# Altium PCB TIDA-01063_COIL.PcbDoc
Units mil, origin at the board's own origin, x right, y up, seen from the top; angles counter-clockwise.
Board outline 2542.15 x 3079.41 mil, 2 copper layers (Top Layer, Bottom Layer), stack 62 mil thick; 9 components, 2 nets, 8 pads, 343 vias.
Unrouted connection lines stored in the file: 1.
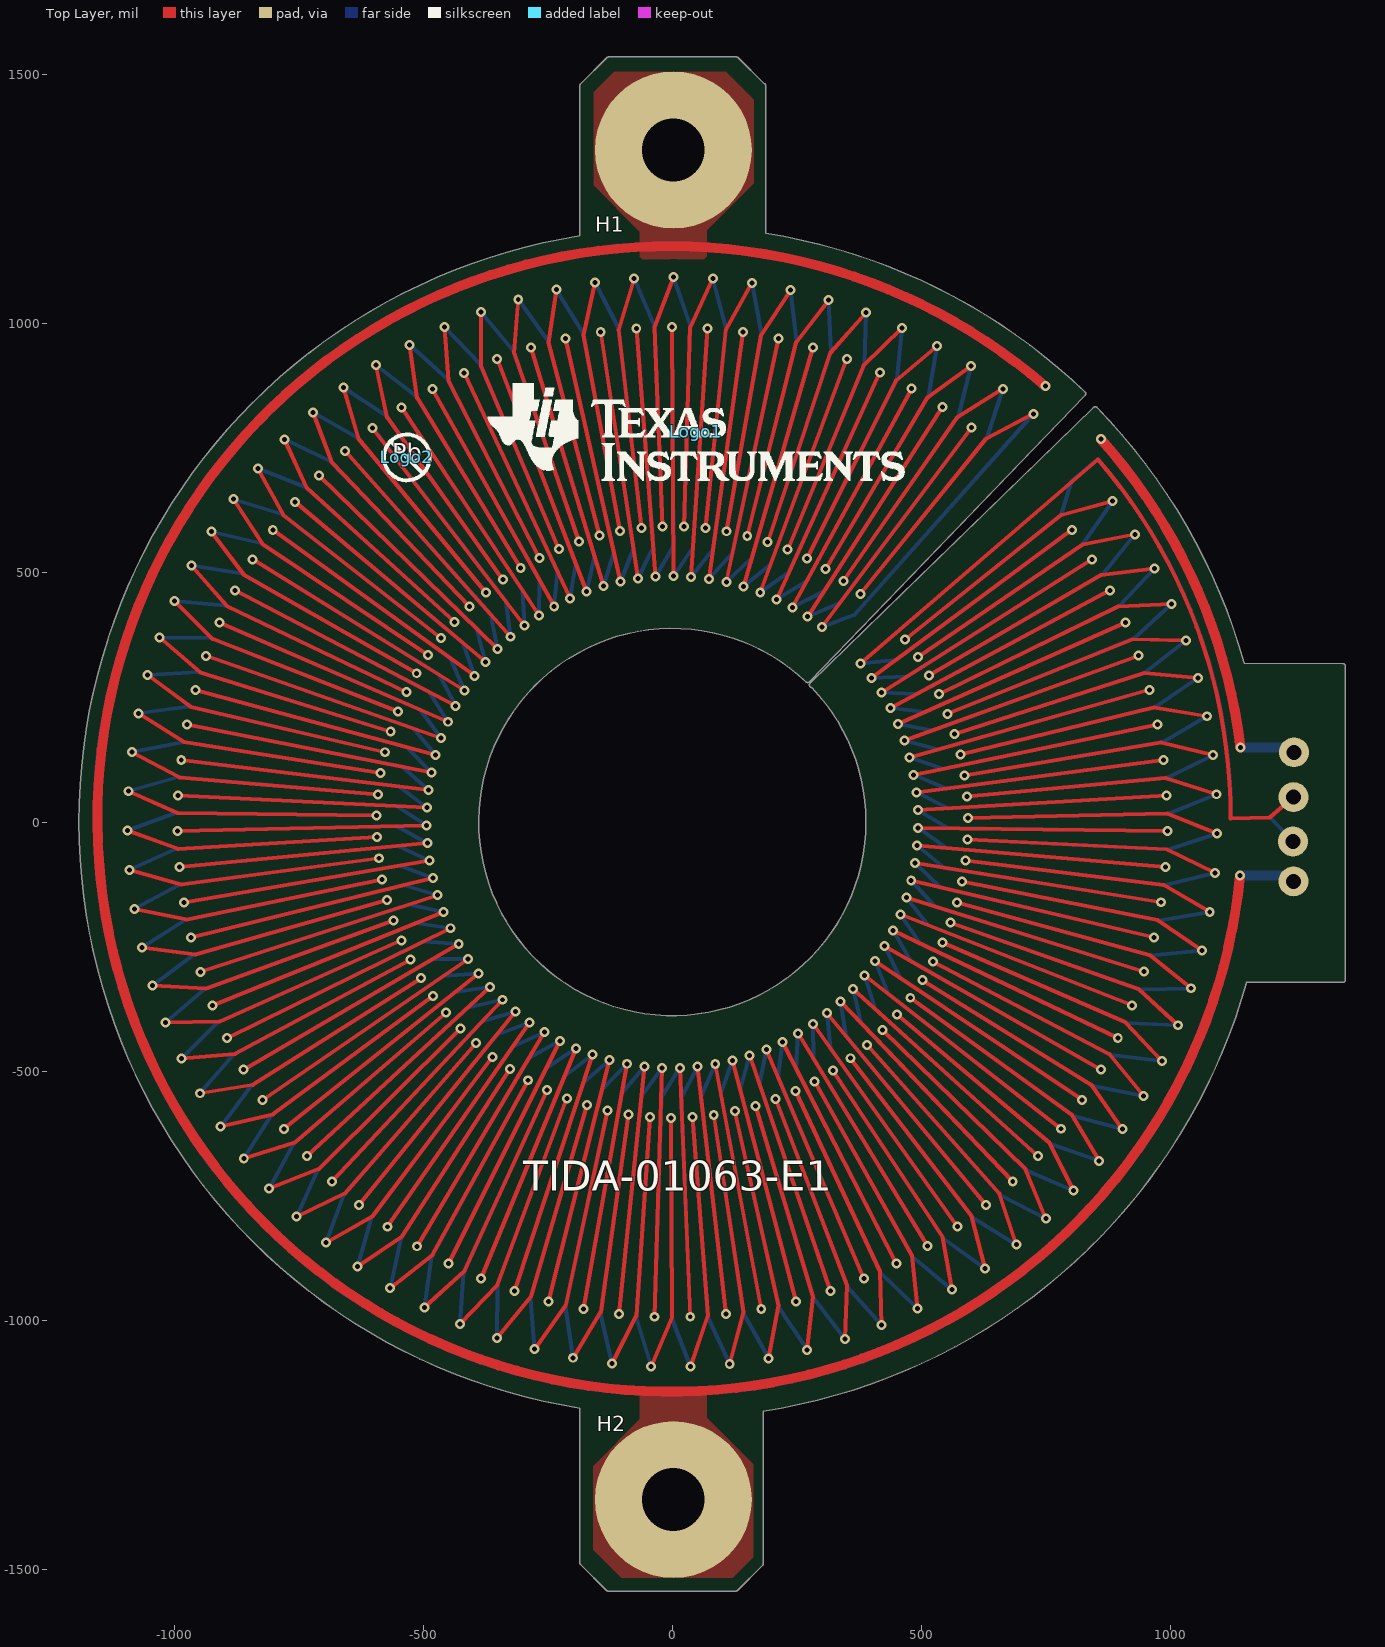
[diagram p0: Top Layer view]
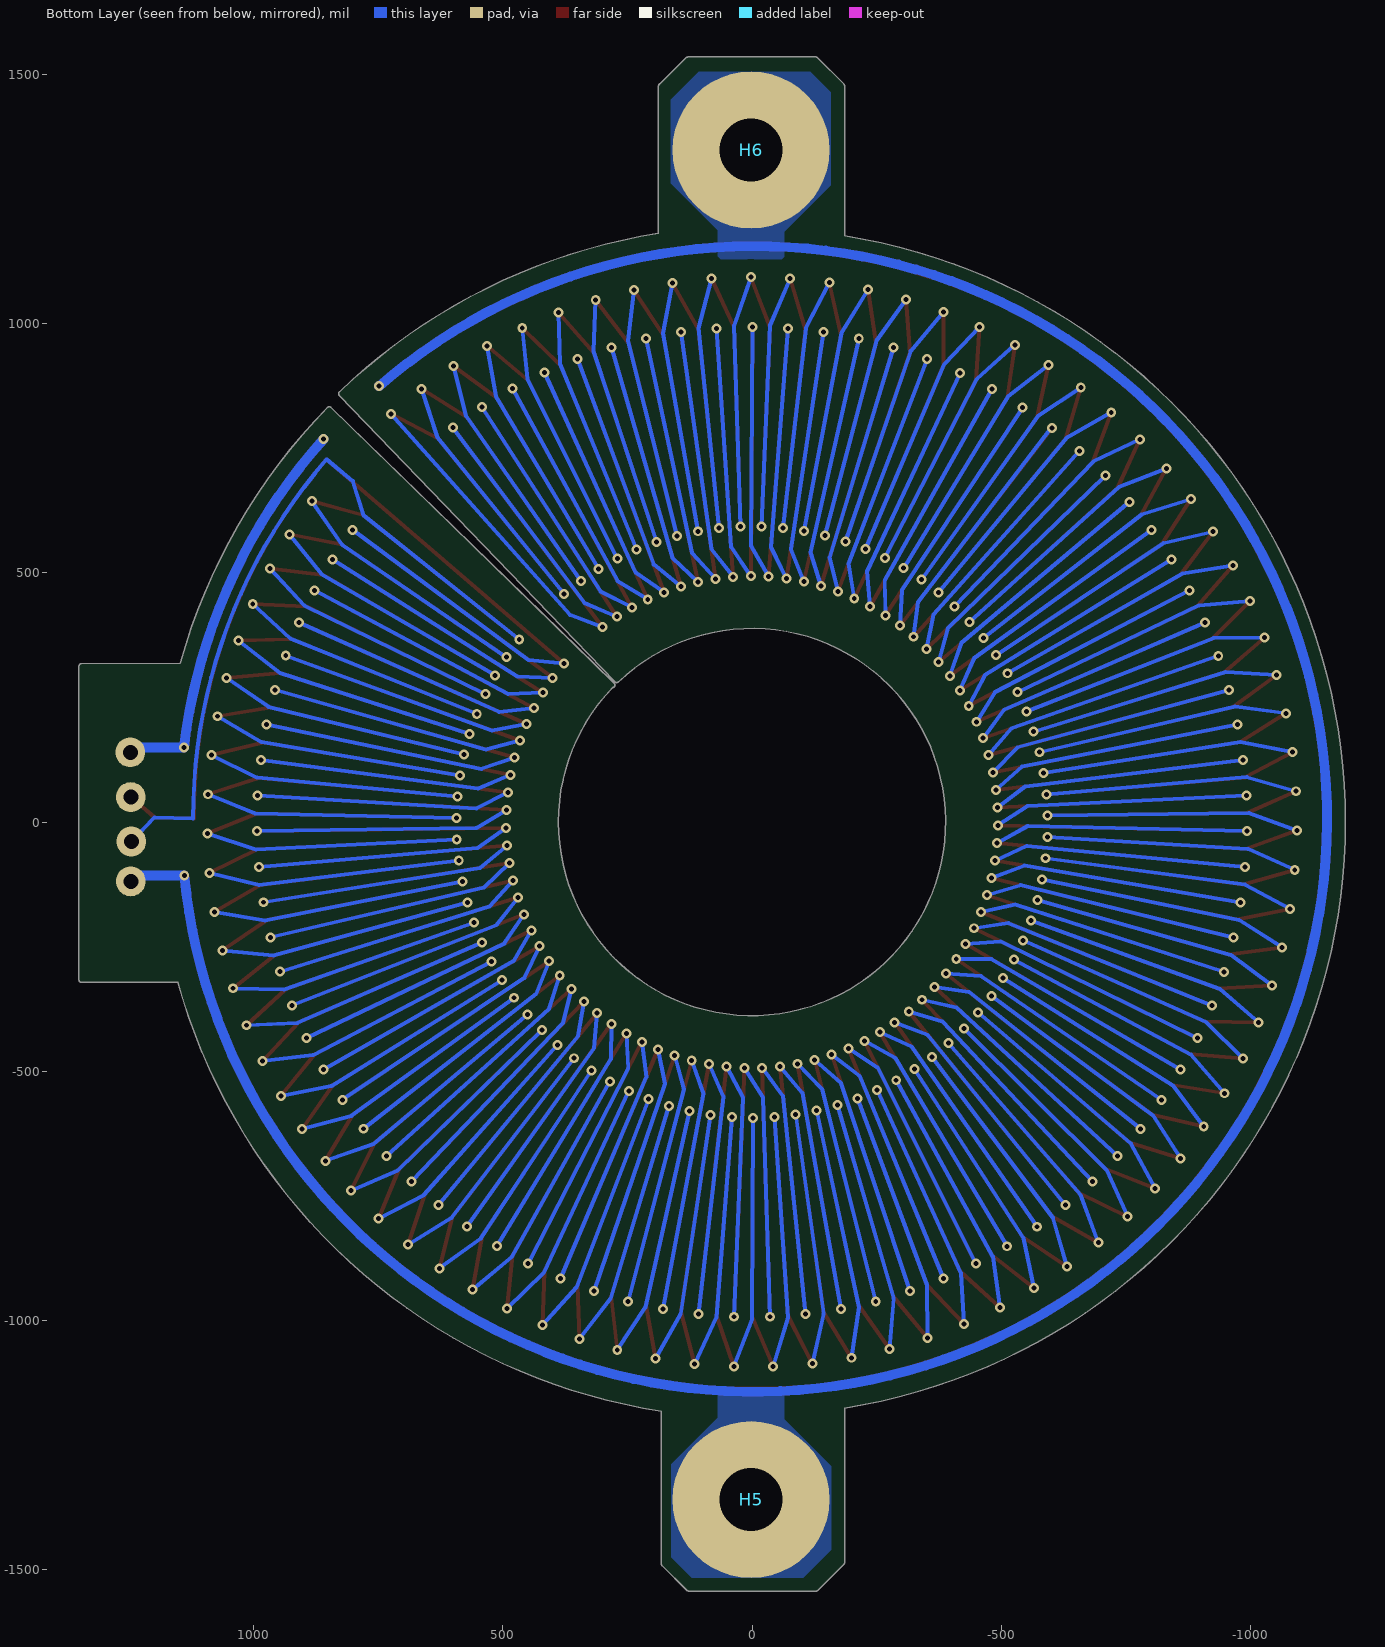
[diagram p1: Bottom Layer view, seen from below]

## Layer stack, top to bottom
Top Solder: solder mask 0.4, Solder Resist, Dk 3.5
Top Layer: signal copper 1.4
Dielectric1: core 59.2, FR-4, Dk 4.8
Bottom Layer: signal copper 1.4
Bottom Solder: solder mask 0.4, Solder Resist, Dk 3.5

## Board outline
-184.35,-1490.35 -132.55,-1542.16 -132.56,-1542.14 ccw(c-129,-1538.61) -129,-1543.63 127.61,-1543.63 ccw(c127.61,-1538.61) 131.17,-1542.14 131.16,-1542.16 180.77,-1492.55 180.75,-1492.56 ccw(c177.22,-1489) 182.24,-1489 182.24,-1182.66 ccw(c0,0) 1152.67,-321.3 1345.98,-321.94 ccw(c1346,-316.92) 1351.02,-316.92 1351.02,313 ccw(c1346,313) 1346.02,318.02 1147.66,318.86 ccw(c0,0) 852.24,832.16 ccw(c848.65,828.65) 845.14,832.23 845.15,832.25 845.14,832.23 277.56,279.62 ccw(c280.89,275.87) 277.22,279.3 276.5,278.59 ccw(c280,275) 279.6,270 cw(c0,0) 388.69,0 cw(c0,0) 268.15,281.37 ccw(c271.61,285) 275.23,281.53 828.44,856.43 ccw(c824.82,859.91) 829.84,859.91 ccw(c824.82,859.91) 828.3,863.53 ccw(c0,0) 187.71,1181.75 187.71,1477.69 ccw(c182.69,1477.69) 184.13,1482.5 132.31,1534.31 132.33,1534.3 ccw(c128.77,1530.77) 128.77,1535.78 -128,1535.78 ccw(c-128,1530.77) -131.56,1534.3 -131.55,1534.31 -184.43,1481.43 -184.41,1481.45 ccw(c-180.88,1477.88) -185.9,1477.88 -185.9,1176.54 ccw(c0,0) -185.82,-1176.55 -185.82,-1486.81 ccw(c-180.81,-1486.81)

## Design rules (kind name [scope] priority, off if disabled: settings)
AcuteAngle [All] p1: minimum=4.50000000000000E+0001 checktracksonly=FALSE
AssemblyTestPointUsage [All] p1: valid=2
Clearance Clearance_BoardEdge_MountingHoles [OnCopper and InComponentClass('Mounting Holes') vs IsKeepOut] p1: gap=40
Clearance Clearance_BoardEdge_Poly [OnCopper and InPoly vs IsKeepOut] p2: gap=25
Clearance Clearance_BoardEdge [OnCopper and Not InComponentClass('Logo') and not InComponentClass('FiducialMark') and not InRegion(1000,500,4000,800) and Not IsKeepout vs IsKeepOut] p3: gap=75
Clearance Clearance_Poly [InPolygon] p4: gap=25
Clearance [All] p5: gap=5
ComponentClearance [All] p1: gap=5 collisioncheckmode=3 verticalgap=5 showdistances=FALSE
DiffPairsRouting [All] p1: maxlimit=100 minlimit=10 mostfreqgap=10 toplayer_minwidth=15 toplayer_maxwidth=15 toplayer_prefwidth=15 bottomlayer_minwidth=15 bottomlayer_maxwidth=15 bottomlayer_prefwidth=15 maxuncoupledlength=1000
FabricationTestPointUsage TestPointUsage [All] p1: valid=2 allowmultiple=FALSE
FabricationTestpoint Testpoint [All] p1: side=3 testpointundercomponent=TRUE minsize=40 maxsize=100 preferedsize=60 minholesize=0 maxholesize=40 preferedholesize=32 testpointgrid=1 allowsidetop=TRUE allowsidebottom=TRUE usegrid=TRUE gridtolerance=0.01
FanoutControl Fanout_LCC [IsLCC] p1: bgadir=Out bgaviamode=Centered fanoutstyle=Auto fanoutdirection=Alternating viagrid=1 // Fanout_LCC (Default Rule)
FanoutControl Fanout_BGA [IsBGA] p2: bgadir=Out bgaviamode=Centered fanoutstyle=Auto fanoutdirection=Alternating viagrid=1 // Fanout_BGA (Default Rule)
FanoutControl Fanout_Default [All] p4: bgadir=Out bgaviamode=Centered fanoutstyle=Auto fanoutdirection=Alternating viagrid=1 // Fanout_Default (Default Rule)
FanoutControl Fanout_Small [(CompPinCount < 5)] p5: bgadir=Out bgaviamode=Centered fanoutstyle=Auto fanoutdirection=OutThenIn viagrid=1 // Fanout_Small (Default Rule)
HoleSize [All] p1: absolutevalues=TRUE maxlimit=251 minlimit=8 maxpercent=80.000 minpercent=20.000
MinimumAnnularRing MinimumAnnularRing_ThermalPadVias [IsVia and InAnyComponent] p1: minimumring=5.91
MinimumAnnularRing [All] p2: minimumring=5
MinimumSolderMaskSliver MinimumSolderMaskSliver_Logo [InComponentClass('Logo') vs InComponentClass('Logo')] p1: minsoldermaskwidth=0.7
MinimumSolderMaskSliver [All] p2: minsoldermaskwidth=3.94
PlaneConnect [All] p1: planeconnectstyle=Direct reliefexpansion=10 reliefentries=4 reliefconductorwidth=10 reliefairgap=10
PolygonConnect [All] p1: connectstyle=Direct reliefconductorwidth=10 reliefentries=4 polygonreliefangle="90 Angle" airgapwidth=10
RoutingVias ThermalPadVias [IsVia and InAnyComponent] p1: holewidth=7.87 width=19.68 viastyle="Through Hole" minholewidth=7.87 minwidth=19.68 maxholewidth=12.99 maxwidth=23.62
RoutingVias [All] p2: holewidth=16 width=32 viastyle="Through Hole" minholewidth=10 minwidth=20 maxholewidth=40 maxwidth=65
SilkToBoardRegionClearance [Not ((IsComment or IsDesignator) And (Hide <> 'False')) and not InRegion(1000,500,4000,800)] p1:
SilkToSilkClearance SilkToSilkClearance_Pb-FreeLogo [(HasFootprint('Pb-Free_Overlay_Medium') OR HasFootprint('Pb-Free_Overlay_Small')) vs (HasFootprint('Pb-Free_Overlay_Medium') OR HasFootprint('Pb-Free_Overlay_Small'))] p1: silktosilkclearance=0
SilkToSilkClearance [All] p2: silktosilkclearance=4
SilkToSolderMaskClearance SilkToComonentPadClearance [IsPad and InAnycomponent] p1: minsilkscreentomaskgap=5 clearancetoexposedcopper=TRUE
SilkToSolderMaskClearance "Silk to Solder Mask Opening" [All] p2: minsilkscreentomaskgap=4 clearancetoexposedcopper=FALSE
SolderMaskExpansion [All] p1: expansion=1.97
UnpouredPolygon [All] p1: allowunpoured=FALSE
Width [All] p1: maxlimit=100 minlimit=6 preferedwidth=10 checkconnectedcopper=TRUE
14 further rules are at their usual default settings.

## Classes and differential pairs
component class AssemblyNote: ZZ2 ZZ3 ZZ4
component class Logo: Logo1
component class "Mounting Holes": H1 H2

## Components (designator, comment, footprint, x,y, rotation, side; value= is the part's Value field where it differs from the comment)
H1 "NY PMS 440 0025 PH" "NY PMS 440 0025 PH" 2,1349 r90 top
H2 "NY PMS 440 0025 PH" "NY PMS 440 0025 PH" 2,-1360 r90 top
H5 "1902C" Keystone_1902C 2,-1360 r90 bottom
H6 "1902C" Keystone_1902C 2,1349 r90 bottom
Logo1 "Texas Instruments" TI_Stacked_Overlay_Small 48,783 r0 top
Logo2 "Pb-Free Symbol" Pb-Free_Overlay_Small -533,732 r0 top
ZZ2 "These assemblies are ESD sensitive, ESD precautions shall be observed." AssemblyNote -671,-1969 r0 top
ZZ3 "These assemblies must be clean and free from flux and all contaminants. Use of no clean flux is not acceptable." AssemblyNote -670,-2068 r0 top
ZZ4 "These assemblies must comply with workmanship standards IPC-A-610 Class 2, unless otherwise specified." AssemblyNote -670,-2148 r0 top

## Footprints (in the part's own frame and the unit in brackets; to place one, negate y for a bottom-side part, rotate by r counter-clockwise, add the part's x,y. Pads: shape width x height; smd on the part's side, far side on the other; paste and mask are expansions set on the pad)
AssemblyNote [mil] "Assembly Note"
Keystone_1902C [mil] "Hex Standoff, 4-40 threaded, nylon"
  round 1 on Mech4: 0(0,0)
  body extent -145,-126 146,126, height 501
"NY PMS 440 0025 PH" [mm] "4-40 nylon screw and mounting hole"
  round 8 hole 3.2: 1(0,0)
  body extent -3.3,-3.3 3.3,3.3, height 2.69
Pb-Free_Overlay_Small [mil]
  silkscreen extent -46,-46 46,46
TI_Stacked_Overlay_Small [mil]
  silkscreen extent -418,-98 418,98

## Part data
H1 H2: "Machine Screw, Round, #4-40 x 1/4, Nylon, Philips panhead"
H5 H6: "Standoff, Hex, 0.5\"L #4-40 Nylon"
Logo1: library part TI_Logo, "Texas Instrument Corporate Signature"
Logo2: library part Pb-Free
ZZ2 ZZ3 ZZ4: library part AssemblyNote

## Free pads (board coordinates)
  round 60 hole 30: 0(1247,-119) 0(1247,50) 0(1248,140) 1(1246,-39)

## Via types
v1: diameter 20, hole 10, Top Layer to Bottom Layer, 343 vias

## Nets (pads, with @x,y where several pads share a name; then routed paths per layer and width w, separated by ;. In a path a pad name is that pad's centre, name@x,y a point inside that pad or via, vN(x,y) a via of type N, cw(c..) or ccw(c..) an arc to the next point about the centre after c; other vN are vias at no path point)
COIL: pad.0@1247,50 pad.1 | length 174207.6
  Top Layer w8: v1(-1093.57,-17.08) -992.25,-53.65 v1(-592.94,-29.99) ; v1(-1091.95,61.85) -993.54,18.07 v1(-593.56,12.87) ; v1(-1089.49,-95.93) -985.8,-125.09 v1(-589.23,-72.68) ; v1(-1084.64,140.47) -989.64,89.7 v1(-591.09,55.66) ; v1(-1079.73,-174.28) -974.2,-195.89 v1(-582.46,-115) ; v1(-1071.68,218.35) -980.59,160.86 v1(-585.53,98.15) ; v1(-1064.34,-251.72) -957.53,-265.66 v1(-572.64,-156.72) ; v1(-1053.14,295.09) -966.43,231.18 v1(-576.92,140.14) ; v1(-1043.41,-327.84) -935.87,-334.04 v1(-559.84,-197.62) ; v1(-1029.11,370.3) -947.24,300.3 v1(-565.31,181.39) ; v1(-1017.04,-402.26) -909.34,-400.69 v1(-544.13,-237.5) ; v1(-999.71,443.57) -923.11,367.85 v1(-550.75,221.7) ; v1(-993.53,-18.35) v1(-493.66,-6.53) ; v1(-992.27,53.37) v1(-492.84,29.1) ; v1(-989.62,-89.98) v1(-491.9,-42.13) ; v1(-985.83,124.82) v1(-489.46,64.58) ; v1(-985.37,-474.59) -878.06,-465.24 v1(-525.58,-276.13) ; v1(-980.55,-161.13) v1(-487.58,-77.5) ; v1(-974.26,195.61) v1(-483.53,99.72) ; v1(-966.37,-231.45) v1(-480.72,-112.48) ; v1(-965.11,514.54) -894.16,433.49 v1(-533.32,260.86) ; v1(-957.61,265.39) v1(-475.07,134.34) ; v1(-948.56,-544.43) -842.21,-527.38 v1(-504.29,-313.33) ; v1(-947.15,-300.56) v1(-471.35,-146.86) ; v1(-935.97,333.78) v1(-464.14,168.26) ; v1(-925.47,582.82) -860.56,496.87 v1(-513.12,298.65) ; v1(-923,-368.11) v1(-459.53,-180.48) ; v1(-909.45,400.43) v1(-450.79,201.31) ; v1(-906.82,-611.45) -801.97,-586.76 v1(-480.37,-348.89) ; v1(-894.04,-433.74) v1(-445.31,-213.17) ; v1(-881.01,648.07) -822.47,557.65 v1(-490.23,334.89) ; v1(-878.19,465) v1(-435.1,233.31) ; v1(-860.42,-497.11) v1(-428.77,-244.74) ; v1(-860.34,-675.27) -757.55,-643.09 v1(-453.95,-382.64) ; v1(-842.36,527.14) v1(-417.13,264.09) ; v1(-831.97,709.94) -780.1,615.53 v1(-464.8,369.38) ; v1(-822.32,-557.88) v1(-410,-275.03) ; v1(-809.38,-735.58) -709.18,-696.06 v1(-425.16,-414.39) ; v1(-802.13,586.54) v1(-396.99,293.49) ; v1(-779.93,-615.75) v1(-389.09,-303.89) ; v1(-778.58,768.11) -733.66,670.21 v1(-436.94,401.95) ; v1(-757.73,642.87) v1(-374.79,321.37) ; v1(-754.21,-792.05) -657.12,-745.41 v1(-394.16,-443.98) ; v1(-733.48,-670.41) v1(-366.15,-331.17) ; v1(-721.14,822.28) -683.4,721.39 v1(-406.8,432.43) ; v1(-709.38,695.86) v1(-350.63,347.57) ; v1(-695.1,-844.4) -601.63,-790.87 v1(-361.1,-471.26) ; v1(-683.2,-721.58) v1(-341.31,-356.72) ; v1(-659.94,872.16) -629.58,768.81 v1(-374.55,460.65) ; v1(-657.33,745.23) v1(-324.64,371.96) ; v1(-632.38,-892.35) -543.01,-832.21 v1(-326.16,-496.08) ; v1(-629.36,-768.99) v1(-314.68,-380.41) ; v1(-601.85,790.7) v1(-296.96,394.41) ; v1(-595.3,917.49) -572.48,812.23 v1(-340.34,486.47) ; v1(-572.25,-812.39) v1(-286.42,-402.12) ; v1(-566.35,-935.64) -481.56,-869.22 v1(-289.52,-518.32) ; v1(-543.24,832.06) v1(-267.73,414.8) ; v1(-527.56,958.05) -512.39,851.41 v1(-304.36,509.75) ; v1(-512.15,-851.55) v1(-256.66,-421.74) ; v1(-497.38,-974.06) -417.6,-901.69 v1(-251.38,-537.86) ; v1(-481.8,869.08) v1(-237.11,433.04) ; v1(-457.07,993.61) -449.63,886.16 v1(-266.79,530.38) ; v1(-449.38,-886.28) v1(-225.57,-439.16) ; v1(-425.81,-1007.4) -351.46,-929.47 v1(-211.92,-554.59) ; v1(-417.85,901.58) v1(-205.25,449.01) ; v1(-384.27,-916.39) v1(-193.3,-454.29) ; v1(-384.2,1024) -384.53,916.28 v1(-227.83,548.25) ; v1(-352.03,-1035.5) -283.49,-952.4 v1(-171.36,-568.43) ; v1(-351.72,929.37) v1(-172.32,462.65) ; v1(-317.16,-941.73) v1(-160.02,-467.05) ; v1(-309.33,1049.05) -317.43,941.64 v1(-187.69,563.25) ; v1(-283.76,952.33) v1(-138.5,473.88) ; v1(-276.41,-1058.2) -214.04,-970.37 v1(-129.91,-579.31) ; v1(-248.4,-962.15) v1(-125.91,-477.37) ; v1(-232.84,1068.63) -248.67,962.08 v1(-146.56,575.33) ; v1(-214.31,970.31) v1(-103.95,482.63) ; v1(-199.35,-1075.38) -143.48,-983.29 v1(-87.77,-587.18) ; v1(-178.34,-977.57) v1(-91.15,-485.21) ; v1(-155.14,1082.64) -178.61,977.52 v1(-104.68,584.4) ; v1(-143.76,983.25) v1(-68.86,488.87) ; v1(-121.25,-1086.96) -72.17,-991.08 v1(-45.19,-591.98) ; v1(-107.35,-987.88) v1(-55.91,-490.53) ; v1(-76.64,1091.01) -107.63,987.85 v1(-62.24,590.43) ; v1(-72.45,991.06) v1(-33.42,492.57) ; v1(-42.52,-1092.87) -0.49,-993.7 v1(-2.36,-593.7) ; v1(-35.81,-993.06) v1(-20.37,-493.28) ; v1(-19.49,593.38) -36.08,993.05 v1(2.27,1093.7) ; v1(-0.76,993.7) v1(2.21,493.7) ; v1(15.27,-493.46) v1(35.93,-993.05) ; v1(23.37,593.24) 35.65,993.06 v1(81.17,1090.68) ; v1(36.43,-1093.09) 71.2,-991.15 v1(40.47,-592.32) ; v1(37.82,492.25) v1(70.93,991.17) ; v1(50.83,-491.08) v1(107.47,-987.87) ; v1(66.11,590.01) 107.2,987.9 v1(159.64,1081.99) ; v1(73.23,488.24) v1(142.25,983.47) ; v1(83.1,-587.86) 142.52,-983.43 v1(115.2,-1087.62) ; v1(86.12,-486.13) v1(178.46,-977.54) ; v1(108.26,481.68) v1(212.82,970.64) ; v1(108.5,583.7) 178.19,977.59 v1(237.28,1067.65) ; v1(120.97,-478.65) v1(248.52,-962.12) ; v1(125.29,-580.33) 213.09,-970.58 v1(193.36,-1076.47) ; v1(142.73,472.62) v1(282.29,952.76) ; v1(150.33,574.35) 248.25,962.19 v1(313.68,1047.75) ; v1(155.18,-468.68) v1(317.28,-941.69) ; v1(166.83,-569.78) 282.56,-952.68 v1(270.51,-1059.72) ; v1(176.45,461.09) v1(350.29,929.91) ; v1(188.59,-456.26) v1(384.39,-916.34) ; v1(191.37,562.01) 317.02,941.78 v1(388.45,1022.39) ; v1(207.5,-556.26) 350.55,-929.81 v1(346.26,-1037.44) ; v1(209.26,447.16) v1(416.46,902.22) ; v1(221.01,-441.47) v1(449.49,-886.23) ; v1(231.41,546.74) 384.13,916.45 v1(461.2,991.7) ; v1(240.97,430.9) v1(480.47,869.82) ; v1(247.09,-539.84) 416.72,-902.1 v1(420.2,-1009.76) ; v1(252.29,-424.37) v1(512.25,-851.49) ; v1(270.25,528.62) 449.24,886.35 v1(531.54,955.85) ; v1(271.43,412.39) v1(541.96,832.9) ; v1(282.24,-405.07) v1(572.35,-812.32) ; v1(285.39,-520.61) 480.71,-869.69 v1(491.95,-976.81) ; v1(300.47,391.74) v1(600.64,791.63) ; v1(307.69,507.75) 512.02,851.63 v1(599.11,915.01) ; v1(310.73,-383.65) v1(629.46,-768.91) ; v1(322.2,-498.66) 542.2,-832.74 v1(561.14,-938.78) ; v1(337.6,-360.23) v1(683.29,-721.5) ; v1(343.51,484.23) 572.12,812.48 v1(663.56,869.41) ; v1(357.34,-474.12) 600.86,-791.46 v1(627.4,-895.85) ; v1(362.71,-334.94) v1(733.56,-670.32) ; v1(377.55,458.19) 629.24,769.09 v1(724.55,819.27) ; v1(377.64,318) 854,728.1 cw(c26.77,12.65) 1120.45,7.54 1199.46,9.54 pad.0@1247,50 ; v1(385.92,-307.9) v1(780,-615.66) ; v1(390.61,-447.1) 656.39,-746.05 v1(690.39,-848.26) ; v1(400.01,289.37) v1(802.06,586.63) ; v1(407.13,-279.26) v1(822.39,-557.78) ; v1(419.84,259.76) v1(842.29,527.24) ; v1(421.85,-417.76) 708.5,-696.75 v1(749.79,-796.24) ; v1(426.22,-249.16) v1(860.48,-497) ; v1(437.49,228.79) v1(878.13,465.1) ; v1(443.08,-217.76) v1(894.1,-433.63) ; v1(450.89,-386.24) 756.92,-643.83 v1(805.28,-740.07) ; v1(452.85,196.63) v1(909.4,400.54) ; v1(457.64,-185.23) v1(923.05,-368) ; v1(465.86,163.45) v1(935.92,333.89) ; v1(467.2,366.33) 779.83,615.87 v1(883.7,644.4) ; v1(469.81,-151.73) v1(947.19,-300.45) ; v1(476.44,129.42) v1(957.57,265.5) ; v1(477.58,-352.7) 801.4,-587.54 v1(856.57,-680.05) ; v1(479.53,-117.45) v1(966.4,-231.33) ; v1(484.53,94.71) v1(974.23,195.73) ; v1(486.75,-82.55) v1(980.57,-161.01) ; v1(490.1,59.51) v1(985.81,124.94) ; v1(491.44,-47.22) v1(989.63,-89.85) ; v1(492.88,330.98) 823.02,556.85 v1(928.7,577.66) ; v1(493.12,24) v1(992.26,53.5) ; v1(493.56,-11.64) v1(993.53,-18.23) ; v1(501.78,-317.33) 841.69,-528.2 v1(903.4,-616.49) ; v1(515.48,294.56) 861.05,496.02 v1(967.96,509.16) ; v1(523.36,-280.31) 877.61,-466.1 v1(945.52,-549.71) ; v1(535.38,256.6) 894.59,432.61 v1(1002.17,438) ; v1(542.22,-241.82) 908.94,-401.57 v1(982.71,-480.06) ; v1(552.5,217.31) 923.47,366.95 v1(1031.15,364.56) ; v1(558.25,-202.07) 935.55,-334.96 v1(1014.78,-407.92) ; v1(566.74,176.89) 947.53,299.37 v1(1054.77,289.22) ; v1(571.38,-161.27) 957.27,-266.59 v1(1041.57,-333.65) ; v1(578.02,135.54) 966.66,230.24 v1(1072.88,212.38) ; v1(581.52,-119.63) 974.01,-196.84 v1(1062.92,-257.64) ; v1(586.29,93.49) 980.75,159.9 v1(1085.41,134.43) ; v1(588.64,-77.37) 985.67,-126.06 v1(1078.74,-180.29) ; v1(591.51,50.95) 989.73,88.73 v1(1092.28,55.77) ; v1(592.69,-34.7) 992.2,-54.62 v1(1088.93,-102) ; v1(593.64,8.14) 993.55,17.1 v1(1093.46,-23.17)
  Bottom Layer w8: v1(-1093.57,-17.08) -997.22,18.12 v1(-593.56,12.87) ; v1(-1091.95,61.85) -993.32,90.01 v1(-591.09,55.66) ; v1(-1089.49,-95.93) -995.93,-53.87 v1(-592.94,-29.99) ; v1(-1084.64,140.47) -980.59,160.86 v1(-585.53,98.15) ; v1(-1079.73,-174.28) -989.45,-125.58 v1(-589.23,-72.68) ; v1(-1071.68,218.35) -970.03,232.02 v1(-576.92,140.14) ; v1(-1064.34,-251.72) -977.81,-196.63 v1(-582.46,-115) ; v1(-1053.14,295.09) -950.76,301.4 v1(-565.31,181.39) ; v1(-1043.41,-327.84) -961.08,-266.66 v1(-572.64,-156.72) ; v1(-1029.11,370.3) -926.54,369.2 v1(-550.75,221.7) ; v1(-1017.04,-402.26) -939.34,-335.3 v1(-559.84,-197.62) ; v1(-999.71,443.57) -897.49,435.08 v1(-533.32,260.86) ; v1(-993.53,-18.35) -553.64,-7.95 v1(-491.9,-42.13) ; v1(-992.27,53.37) -552.77,32.01 v1(-493.66,-6.53) ; v1(-989.62,-89.98) -551.63,-47.87 v1(-487.58,-77.5) ; v1(-985.83,124.82) -549.02,71.81 v1(-492.84,29.1) ; v1(-985.37,-474.59) -912.7,-402.19 v1(-544.13,-237.5) ; v1(-980.55,-161.13) -546.74,-87.54 v1(-480.72,-112.48) ; v1(-974.26,195.61) -542.41,111.23 v1(-489.46,64.58) ; v1(-966.37,-231.45) -539,-126.75 v1(-471.35,-146.86) ; v1(-965.11,514.54) -863.76,498.69 v1(-513.12,298.65) ; v1(-957.61,265.39) -532.98,150.07 v1(-483.53,99.72) ; v1(-948.56,-544.43) -881.31,-466.99 v1(-525.58,-276.13) ; v1(-947.15,-300.56) -528.45,-165.31 v1(-459.53,-180.48) ; v1(-935.97,333.78) -520.76,188.13 v1(-475.07,134.34) ; v1(-925.47,582.82) -825.54,559.71 v1(-490.23,334.89) ; v1(-923,-368.11) -515.15,-203 v1(-445.31,-213.17) ; v1(-909.45,400.43) -505.83,225.21 v1(-464.14,168.26) ; v1(-906.82,-611.45) -845.32,-529.35 v1(-504.29,-313.33) ; v1(-894.04,-433.74) -499.16,-239.63 v1(-428.77,-244.74) ; v1(-881.01,648.07) -783.01,617.8 v1(-464.8,369.38) ; v1(-878.19,465) -488.27,261.11 v1(-450.79,201.31) ; v1(-860.42,-497.11) -480.57,-275.02 v1(-410,-275.03) ; v1(-860.34,-675.27) -804.93,-588.95 v1(-480.37,-348.89) ; v1(-842.36,527.14) -468.16,295.65 v1(-435.1,233.31) ; v1(-831.97,709.94) -736.4,672.68 v1(-436.94,401.95) ; v1(-822.32,-557.88) -459.48,-308.97 v1(-389.09,-303.89) ; v1(-809.38,-735.58) -760.35,-645.49 v1(-453.95,-382.64) ; v1(-802.13,586.54) -445.61,328.66 v1(-417.13,264.09) ; v1(-779.93,-615.75) -435.99,-341.32 v1(-366.15,-331.17) ; v1(-778.58,768.11) -685.95,724.05 v1(-406.8,432.43) ; v1(-757.73,642.87) -420.74,359.95 v1(-396.99,293.49) ; v1(-754.21,-792.05) -711.8,-698.66 v1(-425.16,-414.39) ; v1(-733.48,-670.41) -410.23,-371.88 v1(-341.31,-356.72) ; v1(-721.14,822.28) -631.93,771.65 v1(-374.55,460.65) ; v1(-709.38,695.86) -393.57,389.47 v1(-374.79,321.37) ; v1(-695.1,-844.4) -659.54,-748.19 v1(-394.16,-443.98) ; v1(-683.2,-721.58) -382.34,-400.51 v1(-314.68,-380.41) ; v1(-659.94,872.16) -574.62,815.23 v1(-340.34,486.47) ; v1(-657.33,745.23) -364.56,416.75 v1(-350.63,347.57) ; v1(-632.38,-892.35) -603.85,-793.82 v1(-361.1,-471.26) ; v1(-629.36,-768.99) -352.45,-427.04 v1(-286.42,-402.12) ; v1@-600.74,791.42 -333.55,441.96 v1(-324.64,371.96) ; v1(-595.3,917.49) -514.31,854.56 v1(-304.36,509.75) ; v1(-572.25,-812.39) -320.72,-451.36 v1(-256.66,-421.74) ; v1(-566.35,-935.64) -545.01,-835.31 v1(-326.16,-496.08) ; v1(-543.24,832.06) -300.76,464.9 v1(-296.96,394.41) ; v1(-527.56,958.05) -451.32,889.44 v1(-266.79,530.38) ; v1(-512.15,-851.55) -287.32,-473.32 v1(-225.57,-439.16) ; v1(-497.38,-974.06) -483.33,-872.45 v1(-289.52,-518.32) ; v1(-481.8,869.08) -266.47,485.36 v1(-267.73,414.8) ; v1(-457.07,993.61) -385.98,919.68 v1(-227.83,548.25) ; v1(-449.38,-886.28) -252.43,-492.81 v1(-193.3,-454.29) ; v1(-425.81,-1007.4) -419.13,-905.05 v1(-251.38,-537.86) ; v1(-417.85,901.58) -230.76,503.32 v1(-237.11,433.04) ; v1(-384.27,-916.39) -216.22,-509.74 v1(-160.02,-467.05) ; v1(-384.2,1024) -318.62,945.13 v1(-187.69,563.25) ; v1(-352.03,-1035.5) -351.46,-929.47 v1(-211.92,-554.59) ; v1(-351.72,929.37) -193.91,518.64 v1(-205.25,449.01) ; v1(-317.16,-941.73) -178.88,-524.01 v1(-125.91,-477.37) ; v1(-309.33,1049.05) -249.61,965.65 v1(-146.56,575.33) ; v1(-283.76,952.33) -155.93,531.29 v1(-172.32,462.65) ; v1(-276.41,-1058.2) -284.52,-955.94 v1(-171.36,-568.43) ; v1(-248.4,-962.15) -140.61,-535.55 v1(-91.15,-485.21) ; v1(-232.84,1068.63) -179.3,981.14 v1(-104.68,584.4) ; v1@-215.08,970.15 -117.2,541.16 v1(-138.5,473.88) ; v1(-199.35,-1075.38) -214.82,-973.98 v1(-129.91,-579.31) ; v1(-178.34,-977.57) -101.61,-544.3 v1(-55.91,-490.53) ; v1(-155.14,1082.64) -108.05,991.52 v1(-62.24,590.43) ; v1(-143.76,983.25) -77.85,548.2 v1(-103.95,482.63) ; v1(-121.25,-1086.96) -143.99,-986.94 v1(-87.77,-587.18) ; v1(-107.35,-987.88) -62.08,-550.21 v1(-20.37,-493.28) ; v1(-76.64,1091.01) -36.24,996.73 v1(-19.49,593.38) ; v1(-72.45,991.06) -38.1,552.39 v1(-68.86,488.87) ; v1(-45.19,-591.98) -72.42,-994.76 v1(-42.52,-1092.87) ; v1(-35.81,-993.06) -22.22,-553.25 v1(15.27,-493.46) ; v1(-33.42,492.57) 1.93,553.7 v1(-0.76,993.7) ; v1(-2.36,-593.7) -0.47,-997.39 v1(36.43,-1093.09) ; v1(2.21,493.7) 41.79,552.12 v1(70.93,991.17) ; v1(2.27,1093.7) 35.76,996.75 v1(23.37,593.24) ; v1(35.93,-993.05) 17.75,-553.42 v1(50.83,-491.08) ; v1(37.82,492.25) 81.51,547.67 v1(142.25,983.47) ; v1(40.47,-592.32) 71.49,-994.82 v1(115.2,-1087.62) ; v1(66.11,590.01) 107.58,991.57 v1(81.17,1090.68) ; v1(73.23,488.24) 120.81,540.36 v1(212.82,970.64) ; v1(83.1,-587.86) 143.07,-987.07 v1(193.36,-1076.47) ; v1(86.12,-486.13) 57.62,-550.69 v1(107.47,-987.87) ; v1(108.26,481.68) 159.48,530.24 v1(282.29,952.76) ; v1(108.5,583.7) 178.83,981.23 v1(159.64,1081.99) ; v1(120.97,-478.65) 97.2,-545.1 v1(178.46,-977.54) ; v1(125.29,-580.33) 213.9,-974.18 v1(270.51,-1059.72) ; v1(142.73,472.62) 197.31,517.35 v1(350.29,929.91) ; v1(150.33,574.35) 249.15,965.77 v1(237.28,1067.65) ; v1(155.18,-468.68) 136.27,-536.67 v1(248.52,-962.12) ; v1(166.83,-569.78) 283.63,-956.21 v1(346.26,-1037.44) ; v1(176.45,461.09) 234.12,501.77 v1(416.46,902.22) ; v1(188.59,-456.26) 174.63,-525.44 v1(317.28,-941.69) ; v1(191.37,562.01) 318.17,945.28 v1(313.68,1047.75) ; v1(207.5,-556.26) 351.87,-933.26 v1(420.2,-1009.76) ; v1(209.26,447.16) 269.71,483.57 v1(480.47,869.82) ; v1(221.01,-441.47) 212.09,-511.47 v1(384.39,-916.34) ; v1(231.41,546.74) 385.54,919.86 v1(388.45,1022.39) ; v1(240.97,430.9) 303.89,462.85 v1(541.96,832.9) ; v1(247.09,-539.84) 418.28,-905.44 v1(491.95,-976.81) ; v1(252.29,-424.37) 248.43,-494.84 v1(449.49,-886.23) ; v1(270.25,528.62) 450.89,889.65 v1(461.2,991.7) ; v1(271.43,412.39) 336.3,439.87 v1(600.64,791.63) ; v1(282.24,-405.07) 283.52,-475.61 v1(512.25,-851.49) ; v1(285.39,-520.61) 482.51,-872.91 v1(561.14,-938.78) ; v1(300.47,391.74) 365.44,415.98 v1(724.55,819.27) ; v1(307.69,507.75) 513.9,854.8 v1(531.54,955.85) ; v1(310.73,-383.65) 317.06,-453.94 v1(572.35,-812.32) ; v1(322.2,-498.66) 544.23,-835.83 v1(627.4,-895.85) ; v1(337.6,-360.23) 348.98,-429.88 v1(629.46,-768.91) ; v1(343.51,484.23) 574.23,815.5 v1(599.11,915.01) ; v1(357.34,-474.12) 603.11,-794.39 v1(690.39,-848.26) ; v1(362.71,-334.94) 379.08,-403.59 v1(683.29,-721.5) ; v1(377.55,458.19) 631.56,771.95 v1(663.56,869.41) ; v1(377.64,318) 448.26,325.04 v1@801.93,586.64 ; v1(385.92,-307.9) 407.21,-375.19 v1(733.56,-670.32) ; v1(390.61,-447.1) 658.84,-748.81 v1(749.79,-796.24) ; v1(400.01,289.37) 470.54,291.85 v1(842.29,527.24) ; v1(407.13,-279.26) 433.33,-344.69 v1(780,-615.66) ; v1(419.84,259.76) 490.24,257.38 v1(878.13,465.1) ; v1(421.85,-417.76) 711.15,-699.33 v1(805.28,-740.07) ; v1(426.22,-249.16) 456.96,-312.68 v1(822.39,-557.78) ; v1(437.49,228.79) 507.64,221.1 v1(909.4,400.54) ; v1(443.08,-217.76) 478.33,-278.9 v1(860.48,-497) ; v1(450.89,-386.24) 759.74,-646.2 v1(856.57,-680.05) ; v1(452.85,196.63) 522.27,183.91 v1(935.92,333.89) ; v1(457.64,-185.23) 497.2,-243.67 v1(894.1,-433.63) ; v1(465.86,163.45) 534.17,145.75 v1(957.57,265.5) ; v1(467.2,366.33) 779.83,615.87 801.39,684.15 854,728.1 ; v1(469.81,-151.73) 513.49,-207.16 v1(923.05,-368) ; v1(476.44,129.42) 543.3,106.83 v1(974.23,195.73) ; v1(477.58,-352.7) 804.38,-589.71 v1(903.4,-616.49) ; v1(479.53,-117.45) 527.09,-169.58 v1(947.19,-300.45) ; v1(484.53,94.71) 549.59,67.36 v1(985.81,124.94) ; v1(486.75,-82.55) 537.95,-131.11 v1(966.4,-231.33) ; v1(490.1,59.51) 553.02,27.54 v1(992.26,53.5) ; v1(491.44,-47.22) 546.01,-91.96 v1(980.57,-161.01) ; v1(492.88,330.98) 823.02,556.85 v1(883.7,644.4) ; v1(493.12,24) 553.56,-12.43 v1(993.53,-18.23) ; v1(493.56,-11.64) 551.22,-52.33 v1(989.63,-89.85) ; v1(501.78,-317.33) 844.83,-530.14 v1(945.52,-549.71) ; v1(515.48,294.56) 864.23,497.88 v1(928.7,577.66) ; v1(523.36,-280.31) 880.87,-467.81 v1(982.71,-480.06) ; v1(535.38,256.6) 897.9,434.24 v1(967.96,509.16) ; v1(542.22,-241.82) 912.33,-403.05 v1(1014.78,-407.92) ; v1(552.5,217.31) 926.89,368.33 v1(1002.17,438) ; v1(558.25,-202.07) 939.02,-336.18 v1(1041.57,-333.65) ; v1(566.74,176.89) 947.53,299.37 v1(1031.15,364.56) ; v1(571.38,-161.27) 960.83,-267.56 v1(1062.92,-257.64) ; v1(578.02,135.54) 970.24,231.11 v1(1054.77,289.22) ; v1(581.52,-119.63) 977.63,-197.55 v1(1078.74,-180.29) ; v1(586.29,93.49) 984.39,160.51 v1(1072.88,212.38) ; v1(588.64,-77.37) 989.33,-126.51 v1(1088.93,-102) ; v1(591.51,50.95) 993.4,89.08 v1(1085.41,134.43) ; v1(592.69,-34.7) 995.88,-54.81 v1(1093.46,-23.17) ; v1(593.64,8.14) 997.24,17.18 v1(1092.28,55.77) ; 853.97,728.08 cw(c28.02,11.15) 1121.72,7.54 1199.46,9.54 pad.1
EARTH: H1.1 H2.1 pad.0@1247,-119 pad.0@1248,140 | length 13880.2
  Top Layer w19.68: v1@748.65,875.01 ccw(c-4.43,6.25) v1(1139.65,-107.53) cw(c-4.43,6.25) v1@1139.17,-112.33 ; v1(860.06,768.98) cw(c14.91,13.33) v1(1140.4,149.53) ccw(c14.91,13.33) 1137.85,169.15
  Bottom Layer w19.68: v1(748.65,875.01) ccw(c-4.53,6.21) v1(1139.65,-107.53) 1235.53,-107.53 pad.0@1247,-119 ; v1(860.06,768.98) cw(c14.91,13.33) v1(1140.4,149.53) 1238.47,149.53 pad.0@1248,140
pads on no net: H5.0 H6.0

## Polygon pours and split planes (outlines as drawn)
EARTH on Top Layer "Bottom Layer-No Net 1" (solid, pour order 8): -117,1506 107,1506 130,1483 163,1450 163,1298 163,1282 69,1188 69,1135.94 63.18,1130.12 -60.06,1130.12 -65.16,1135.22 -65.16,1185.16 -158,1278 -158,1387 -158,1465
EARTH on Top Layer "Bottom Layer-No Net 1" (solid, pour order 7): 121,-1517 -103,-1517 -126,-1494 -159,-1461 -159,-1309 -159,-1293 -65,-1199 -65,-1146.94 -59.18,-1141.12 64.06,-1141.12 69.16,-1146.22 69.16,-1196.16 162,-1289 162,-1398 162,-1476
EARTH on Bottom Layer "Bottom Layer-No Net 1" (solid, pour order 6): -117,1506 107,1506 130,1483 163,1450 163,1298 163,1282 69,1188 69,1135.94 63.18,1130.12 -60.06,1130.12 -65.16,1135.22 -65.16,1185.16 -158,1278 -158,1387 -158,1465
EARTH on Bottom Layer "Bottom Layer-No Net 1" (solid, pour order 5): 121,-1517 -103,-1517 -126,-1494 -159,-1461 -159,-1309 -159,-1293 -65,-1199 -65,-1146.94 -59.18,-1141.12 64.06,-1141.12 69.16,-1146.22 69.16,-1196.16 162,-1289 162,-1398 162,-1476

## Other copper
Top Layer:
  text "Top Layer" at -4753,-5618.49 h60
Bottom Layer:
  text "Bottom Layer" at -4753,-5618.49 h60

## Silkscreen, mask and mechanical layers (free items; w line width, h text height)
Top Overlay:
  text "TIDA-01063-E1" at -299.54,-740.06 h60
  text ".Layer_Name" at -4753,-5618.49 h60
Bottom Overlay:
  text ".Layer_Name" at -4753,-5618.49 h60
Top Paste:
  text ".Layer_Name" at -4753,-5618.49 h60
Bottom Paste:
  text ".Layer_Name" at -4753,-5618.49 h60
Top Solder:
  text ".Layer_Name" at -4753,-5618.49 h60
  text ".Layer_Name" at -4753,-5618.49 h60
Bottom Solder:
  text ".Layer_Name" at -4753,-5618.49 h60
M1 Board Outline:
  lines w10: -180.88,1172.24 ccw(c0,0) -180.81,-1172.26 -180.81,-1486.81 -129,-1538.61 127.61,-1538.61 177.22,-1489 177.22,-1181.9 181.42,-1177.71 ccw(c0,0) 1148.86,-316.28 1346,-316.92 1346,313 1143.84,313.86 ccw(c0,0) 848.65,828.65 280.89,275.87 cw(c0,0) 271.61,285 824.82,859.91 ccw(c0,0) 182.69,1177.46 182.69,1477.69 183,1478 181.53,1478 128.77,1530.77 -128,1530.77 -180.88,1477.88 -180.88,1172.24
M2 Board Dimensions:
  rectangle: -5205,-5160 -4830,-5035
  rectangle: -5330,-5035 -5205,-4910
  lines w7: -5330,-5035 -4330,-5035 ; -5330,-4910 -5330,-5160 -4330,-5160 -4330,-4910 ; -5205,-5160 -5205,-4910 ; -5080,-5160 -5080,-4910 ; -4830,-5160 -4830,-4910 ; -4580,-5160 -4580,-4910
M5 Assembly Top:
  lines w10: -5622,-5690.17 978,-5690.17 ; -5622,-5486.83 980,-5486.83 ; -5622,-5283.5 -5622,-5893.5 -1617,-5893.5 980,-5893.5 980,-5283.5 -5621.5,-5283.5 -5621.5,-5893.5 -4046,-5893.5 ; -3157,-5893.5 -3157,-5283.5 ; -1890,-5486.83 -1890,-5283.5 ; -1050,-5486.83 -1050,-5283.5 ; -428,-5900 -428,-5697.17
  text "COMPONENTS MARKED 'DNP' SHOULD NOT BE POPULATED." at -4176.5,-5078.5 h60
  text "ASSEMBLY VARIANT:" at -4177,-5194 h60
  text ".VariantName" at -3141,-5194 h60
  text "PCB VIEWED FROM TOP SIDE" at -5558.5,-5415.67 h60
  text "BOARD #:" at -3082,-5415.67 h60
  text "TIDA-01603-Coil" at -2536.5,-5415.67 h30
  text "REV:" at -1692,-5415.67 h60
  text "E1" at -1400.5,-5415.67 h60
  text "SVN REV:" at -854,-5415.67 h60
  text ".VersionControl_RevNumber" at -348,-5415.67 h60
  text "M5 Assembly Top" at -4735,-5610 h60
  text "LAYER NAME =" at -5558.5,-5618.49 h60
  text "TID #:" at -3082,-5619 h60
  text "TIDA-01063-coil" at -2536.5,-5619 h60
  text "PLOT NAME =" at -5558.5,-5824.34 h60
  text ".plot_File_Name" at -4753,-5824.34 h60
  text "GENERATED    :" at -3080,-5824.34 h60
  text ".Print_Date" at -2210.5,-5824.34 h60
  text ".Print_Time" at -1481.5,-5824.34 h60
  text "TEXAS INSTRUMENTS" at -217,-5824.34 h60
M6 Assembly Bottom:
  lines w10: -5622.5,-5487.33 979.5,-5487.33 ; -5620.5,-5690.67 979.5,-5690.67 ; -4214.5,-5900.5 -4214.5,-5697.67 ; -3592.5,-5487.33 -3592.5,-5284 ; -2752.5,-5487.33 -2752.5,-5284 ; -1485.5,-5894 -1485.5,-5284 ; -596.5,-5894 979,-5894 979,-5284 -5622.5,-5284 -5622.5,-5894 -3025.5,-5894 979.5,-5894 979.5,-5284
  text "COMPONENTS MARKED 'DNP' SHOULD NOT BE POPULATED." at 772,-5078 h60
  text ".VariantName" at -272,-5194 h60
  text "ASSEMBLY VARIANT:" at 767,-5194 h60
  text ".VersionControl_RevNumber" at -4294.5,-5416.17 h60
  text "SVN REV:" at -3788.5,-5416.17 h60
  text ".PCB_Rev" at -3242,-5416.17 h60
  text "REV:" at -2950.5,-5416.17 h60
  text ".PRJ_Number" at -2106,-5416.17 h30
  text "BOARD #:" at -1560.5,-5416.17 h60
  text "PCB VIEWED FROM BOTTOM SIDE" at 916,-5416.17 h60
  text "M6 Assembly Bottom" at 89,-5612 h60
  text ".TID" at -2106,-5619.5 h60
  text "TID #:" at -1560.5,-5619.5 h60
  text "LAYER NAME =" at 912.5,-5620.49 h60
  text "TEXAS INSTRUMENTS" at -4425.5,-5824.84 h60
  text ".Print_Time" at -3161,-5824.84 h60
  text ".Print_Date" at -2432,-5824.84 h60
  text "GENERATED    :" at -1562.5,-5824.84 h60
  text ".plot_File_Name" at 110.5,-5824.84 h60
  text "PLOT NAME =" at 916,-5824.84 h60
M9 Title Sheet:
  drawing of 57 lines, arcs and shapes, not listed
  text "1" at -4590.16,3276.5 h70
  text "2" at -2094.5,3276.5 h70
  text "3" at 394.84,3276.5 h70
  text "4" at 2901.51,3276.5 h70
  text "5" at 5400.5,3276.5 h70
  text "6" at 7905.5,3276.5 h70
  text "A" at -5746.5,2133.5 h70
  text "A" at 9053.5,2133.5 h70
  text "B" at -5746.5,-246.5 h70
  text "B" at 9053.5,-246.5 h70
  text "C" at -5746.5,-2621.5 h70
  text "C" at 9053.5,-2621.5 h70
  text "PROJECT TITLE:" at 6013.5,-4482.5 h45
  text "TIDA-01063-Rogowski Coil" at 6063.5,-4615.83 h70
  text "DESIGNED FOR:" at 6013.5,-4783.5 h45
  text "TIDA-01063-Rogowski Coil" at 6063.5,-4923.5 h70
  text "D" at -5746.5,-4991.5 h70
  text "D" at 9053.5,-4991.5 h70
  text "FILE NAME:" at 6013.5,-5083.5 h45
  text "TIDA-01063-Coil" at 6063.5,-5203.5 h70
  text "Texas Instruments (TI) and/or its licensors do not warrant the accuracy or completeness of this specification" at 1044,-5365.34 h45
  text "ENGINEER:" at 6013.5,-5373.5 h45
  text "LAYOUT BY:" at 7518.5,-5373.5 h45
  text "or any information contained therein. TI and/or its licensors do not warrant that this design will meet" at 999.01,-5478 h45
  text "Srinivasan Iyer" at 6063.5,-5528.49 h70
  text "Avinash N" at 7569,-5528.49 h70
  text "the specifications, will be suitable for your application or fit for any particular purpose, or will operate in" at 999.01,-5590.67 h45
  text "ALTIUM DESIGNER VERSION:" at 7518.5,-5683.5 h45
  text "an implementation. TI and/or its licensors do not warrant that the design is production worthy. You should" at 999.01,-5703.33 h45
  text "completely validate and test your design implementation to confirm the system functionality for your application." at 1044,-5816 h45
  text ".print_Scale" at 6063.5,-5816.83 h70
  text ".Application_BuildNumber" at 7569,-5816.83 h70
  text "1" at -4590.16,-6023.5 h70
  text "2" at -2094.5,-6023.5 h70
  text "3" at 394.84,-6023.5 h70
  text "4" at 2901.51,-6023.5 h70
  text "5" at 5400.5,-6023.5 h70
  text "6" at 7905.5,-6023.5 h70
M10 Fab Notes:
  drawing of 228 lines, arcs and shapes, not listed
  text "DESIGN INFORMATION" at 7050.02,2050 h60
  text "(REFER ALSO ARRAY/PANEL PROFILING INFORMATION)" at 6688.46,1888.29 h60
  text "BOARD SIZE" at 6002.46,1884 h60
  text "77.96MM" at 7195,1764 h60
  text "64.32MM" at 6480,1763 h60
  text "X" at 6970.46,1756.18 h60
  text "Number of Layers :" at 6405.46,1559 h60
  text "2" at 7500.27,1549 h60
  text "MIN. TRACK WIDTH:" at 6405.46,1420 h60
  text "8" at 7501.7,1420 h60
  text "MIL" at 7656.46,1420 h60
  text "5" at 7460.1,1304.82 h60
  text "MIN. CLEARANCE:" at 6405.46,1288 h60
  text "MIL" at 7656.46,1288 h60
  text "12" at 7472.28,1164.9 h60
  text "MIN. VIA DRILL SIZE:" at 6405.46,1156 h60
  text "MIL" at 7656.46,1156 h60
  text "5 MIL" at 7100.46,1014.29 h60
  text "MINIMUM ANNULAR RING" at 6076.23,1010 h60
  text "EXTERNAL" at 7808.46,1010 h60
  text "PER" at 6276.23,892 h60
  text "IPC-D-275 CLASS 2 LEVEL C" at 6496.23,892 h60
  text "MIL, HOLES" at 7984.46,779.71 h60
  text "+/-" at 7592,779 h60
  text "+/-" at 8446,779 h60
  text "REGISTRATION TOLERANCES:" at 6076.23,774 h60
  text "METAL" at 7276,774 h60
  text "5" at 7852.2,774 h60
  text "3" at 8685.2,774 h60
  text "MIL" at 8801.46,774 h60
  text "MATERIAL:" at 6001.46,564.54 h60
  text "FR-4 High Tg" at 6987.9,424.21 h60
  text "FR-408" at 6422.46,415.64 h60
  text "X" at 6829,416 h60
  text "OTHER" at 7910.46,415.64 h60
  text "63 MIL (1.6mm) +/-10%" at 6742.56,252.92 h60
  text "THICKNESS:" at 6076.23,248.64 h60
  text "X" at 6614.4,248.64 h60
  text "OTHER" at 8027.46,248.64 h60
  text "TOLERANCE:" at 6076.23,90.64 h60
  text "X" at 6915.53,90.64 h60
  text "ANSI IPC-6012 TYPE 3 CLASS 2" at 7102.48,90.64 h60
  text "OTHER +/-" at 7102.46,-65.36 h60
  text "BOW & TWIST:" at 6076.23,-222.36 h60
  text "X" at 6915.53,-222.36 h60
  text "ANSI IPC-6012 TYPE 3 CLASS 2" at 7102.48,-222.36 h60
  text "OTHER +/-" at 7102.46,-380.87 h60
  text "COPPER THICKNESS (FINISHED):" at 6001.46,-516.36 h60
  text "1.4MIL (1oz)" at 6881.46,-669.08 h60
  text "2MIL (1.4oz)" at 7648.46,-669.08 h60
  text "2.8MIL (2oz)" at 8375.46,-669.08 h60
  text "OUTER:" at 6358.46,-673.36 h60
  text "X" at 6753,-674 h60
  text "1.4MIL (1oz)" at 6881.46,-826.08 h60
  text "2.8MIL (2oz)" at 7648.46,-826.08 h60
  text "N/A" at 8375,-825.71 h60
  text "INNER SIGNAL:" at 6069.38,-830.36 h60
  text "DRILLING:" at 6001.46,-969.36 h60
  text "REFERENCE:" at 6076.23,-1086.36 h60
  text "X" at 6724.46,-1086.36 h60
  text "AS SHOWN" at 6911.46,-1086.36 h60
  text "X" at 7625.46,-1086.36 h60
  text "NC_DRILL FILES" at 7762.46,-1086.36 h60
  text "PTH MIN COPPER THICKNESS:" at 6076.23,-1244.36 h60
  text "X" at 7426.46,-1244.36 h60
  text "1MIL" at 7563.46,-1244.36 h60
  text "OTHER" at 8060.46,-1244.36 h60
  text "BOARD FINISH:" at 6001.46,-1403.36 h60
  text "SILKSCREEN:" at 6156.68,-1521.36 h60
  text "X" at 7105.46,-1521.36 h60
  text "TOP" at 7231.46,-1521.36 h60
  text "BOTTOM" at 7742.46,-1521.36 h60
  text "SILKSCREEN COLOR:" at 6156.68,-1688.36 h60
  text "X" at 7104.42,-1688.36 h60
  text "WHITE" at 7231.46,-1688.36 h60
  text "OTHER" at 7742.46,-1688.36 h60
  text "SOLDER RESIST COLOR:" at 6156.68,-1858.36 h60
  text "X" at 6724.42,-2017.56 h60
  text "GREEN" at 6851.46,-2017.56 h60
  text "BLUE" at 7442.46,-2017.56 h60
  text "OTHER" at 7980.46,-2017.56 h60
  text "IMMERSION GOLD (ENIG)" at 7062.46,-2206.08 h60
  text "ENEPIG" at 8400,-2209.36 h60
  text "SURFACE FINISH:" at 6001.46,-2210.36 h60
  text "X" at 6875.51,-2210.36 h60
  text "IMM. TIN/SILVER OR EQUIV" at 6331,-2367.36 h60
  text "OTHER" at 7762.46,-2367.36 h60
  text "ARRAY/PANEL:" at 6001.46,-2546.36 h60
  text "CUT AND TRIM PER MECH LAYER 1" at 7062.46,-2550.65 h60
  text "N.C. ROUTE" at 7062.46,-2702.36 h60
  text "X" at 7741.46,-2702.36 h60
  text "V. SCORE" at 7928.46,-2702.36 h60
  text "CERTIFICATION:" at 6001.46,-2839.36 h60
  text "MATERIALS AND WORKMANSHIP FOR ALL PCBS" at 6726.46,-2839.36 h60
  text "TO MEET OR EXCEED THE REQUIREMENTS OF:" at 6726.46,-2937.36 h60
  text "X" at 6352.96,-3073.87 h60
  text "ANSI IPC-A-600F CLASS ->" at 6491.96,-3073.87 h60
  text "X" at 8131.02,-3073.87 h60
  text "2" at 8249.96,-3073.86 h60
  text "1" at 7934.96,-3075.36 h60
  text "3" at 8603.96,-3075.36 h60
  text "X" at 6355.02,-3233.36 h60
  text "UL 94V-0" at 6491.96,-3233.36 h60
  text "X" at 7167.02,-3233.36 h60
  text "RoHS" at 7303.96,-3233.36 h60
  text "OTHER" at 7948.36,-3233.36 h60
  text "PER ORDER" at 8345.42,-3233.36 h60
  text "X" at 8297.28,-3365.1 h60
  text "VIA TENTING:" at 7219,-3367 h60
  text "ADDITIONAL REQUIREMENTS:" at 6001.46,-3374.36 h60
  text "YES" at 7768.67,-3376.08 h60
  text "NO" at 8133.47,-3381.31 h60
  text "MICROSECTION:" at 6076.23,-3489.36 h60
  text "YES" at 6981.96,-3489.36 h60
  text "IMPEDANCE CONTROL:" at 7241,-3496 h60
  text "YES" at 8225,-3497 h60
  text "X" at 8767,-3504 h60
  text "NO" at 8600.47,-3514.31 h60
  text "REQUIRED" at 7843.46,-3645.51 h60
  text "BARE BOARD ELEC. TEST:" at 6076.23,-3648.36 h60
  text "NONE" at 7381.96,-3648.36 h60
  text "X" at 7716.46,-3648.36 h60
  text "PER ORDER" at 8435.46,-3648.36 h60
  text "MANUFACTURER'S UL:" at 6076.23,-3805.36 h60
  text "RAIL" at 7241.96,-3809.65 h60
  text "METAL" at 7733.77,-3809.65 h60
  text "X" at 8109,-3810 h60
  text "SILK" at 8245.46,-3809.65 h60
M11 Gerber Information:
  lines w10: -5622,-5690.17 978,-5690.17 ; -5622,-5486.83 980,-5486.83 ; -5622,-5283.5 -5622,-5893.5 -1617,-5893.5 980,-5893.5 980,-5283.5 -5621.5,-5283.5 -5621.5,-5893.5 -4046,-5893.5 ; -3157,-5893.5 -3157,-5283.5 ; -1890,-5486.83 -1890,-5283.5 ; -1050,-5486.83 -1050,-5283.5 ; -428,-5900 -428,-5697.17
  text "ALL ARTWORK VIEWED FROM TOP SIDE" at -5558.5,-5415.67 h60
  text "BOARD #:" at -3082,-5415.67 h60
  text "TIDA-01063-coil" at -2536.5,-5415.67 h40
  text "REV:" at -1692,-5415.67 h60
  text "E1" at -1400.5,-5415.67 h60
  text "SVN REV:" at -854,-5415.67 h60
  text ".VersionControl_RevNumber" at -348,-5415.67 h60
  text "LAYER NAME =" at -5558.5,-5618.49 h60
  text "TID #:" at -3082,-5619 h60
  text "TIDA-01063-coil" at -2536.5,-5619 h60
  text "PLOT NAME =" at -5558.5,-5824.34 h60
  text ".plot_File_Name" at -4753,-5824.34 h60
  text "GENERATED    :" at -3080,-5824.34 h60
  text ".Print_Date" at -2210.5,-5824.34 h60
  text ".Print_Time" at -1481.5,-5824.34 h60
  text "TEXAS INSTRUMENTS" at -217,-5824.34 h60
M12 Stackup:
  lines w6: 6007,2704 8557,2704 ; 6007,2808.4 8557,2808.4 ; 5947,2219 ccw(c5981,2219) 5981,2185 8583,2185 ccw(c8583,2219) 8617,2219 8617,2925 ccw(c8583,2925) 8583,2959 5981,2959 ccw(c5981,2925) 5947,2925 5947,2219
  text "Layer Stack Up Detail for: TIDA-01063_Coil_E1" at 6007,2841.1 h57
  text "Layer" at 6007,2769.4 h24
  text "Gerber" at 6902.81,2769.4 h24
  text "Copper" at 7466.33,2769.4 h24
  text "Dielectric" at 8069.04,2769.4 h24
  text "Name" at 6007,2721.4 h24
  text "Document" at 6902.81,2721.4 h24
  text "Thickness" at 7466.33,2721.4 h24
  text "Material" at 8069.04,2721.4 h24
  text "Top Solder Mask" at 6007,2628.44 h34
  text "(.GTS)" at 6902.81,2628.44 h34
  text "Solder Resist" at 8069.04,2628.44 h34
  text "Top Layer" at 6007,2531.69 h34
  text "(.GTL)" at 6902.81,2531.69 h34
  text "1.4mil" at 7466.33,2531.69 h34
  text "FR-4 High Tg" at 8098,2531 h34
  text "FR-4 High Tg" at 8100,2312 h34
  text "Bottom Layer" at 6013,2302 h34
  text "(.GBL)" at 6911,2301 h34
  text "1.4mil" at 7471,2295 h34
  text "Solder Resist" at 8085,2224 h34
  text "(.GBS)" at 6930,2217 h34
  text "Bottom Solder Mask" at 6039,2216 h34
M13 Component Bodies Top:
  text ".Layer_Name" at -4753,-5618.49 h60
M14 Component Bodies Bottom:
  text ".Layer_Name" at -4753,-5618.49 h60
M15 Courtyards Top:
  text ".Layer_Name" at -4753,-5618.49 h60
M16 Courtyards Bottom:
  text ".Layer_Name" at -4753,-5618.49 h60
Drill Drawing:
  text ".legend" at -818.1,-2502.82 h60
  text "Drill Table" at -821.1,-2673.82 h60
  text "FOR 10MIL DRILL +0/-10MIL" at -793.1,-2879.82 h60
  text "FOR PTH DRILL +/-3MIL" at -786.82,-2985.92 h60
  text ".Layer_Name" at -4753,-5618.49 h60

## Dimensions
2,-1360 to 1346,-1590 on M1 Board Outline
-5330,-5160 to -4330,-5160 on M2 Board Dimensions
-393.7,0 to -6022,-6294 on M2 Board Dimensions
1346,313 to 1346,-316.92 on M2 Board Dimensions
-180.88,1172.24 to -180.88,1477.88 on M2 Board Dimensions
-180.88,1477.88 to 182.69,1477.69 on M2 Board Dimensions
1143.84,313.86 to 1346,313 on M2 Board Dimensions
1346,-316.92 to -1186.12,0 on M2 Board Dimensions
-128,1530.77 to -129,-1538.61 on M2 Board Dimensions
